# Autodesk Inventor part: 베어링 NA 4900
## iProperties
Created: 2009-02
Part Number: 베어링 NA 4900
Material: Steel, Mild
Description: 니들 롤러 베어링 - 경계 치수 및 공차
Document SubType Name: Modeling
Standard: KS B 2029
Designer: SeoGD™
Standards Organization: KS
Language: ko-KR
Size Designation: NA 4900 - 10 x 22 x 13
Categories: <MemberInstance><Categories><Category DisplayName="샤프트 부품" InternalName="7f7aeb1f-a693-4053-b835-cee3144e0d98" Mnemonic="SHFT"><Category DisplayName="베어링" Inter
Density: 1 g/cm^3
IsCustomPart: 0
Author: SeoGD™
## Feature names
1. IDS_ARRAYROLLER[SIMPL:T] [Circular Pattern]
